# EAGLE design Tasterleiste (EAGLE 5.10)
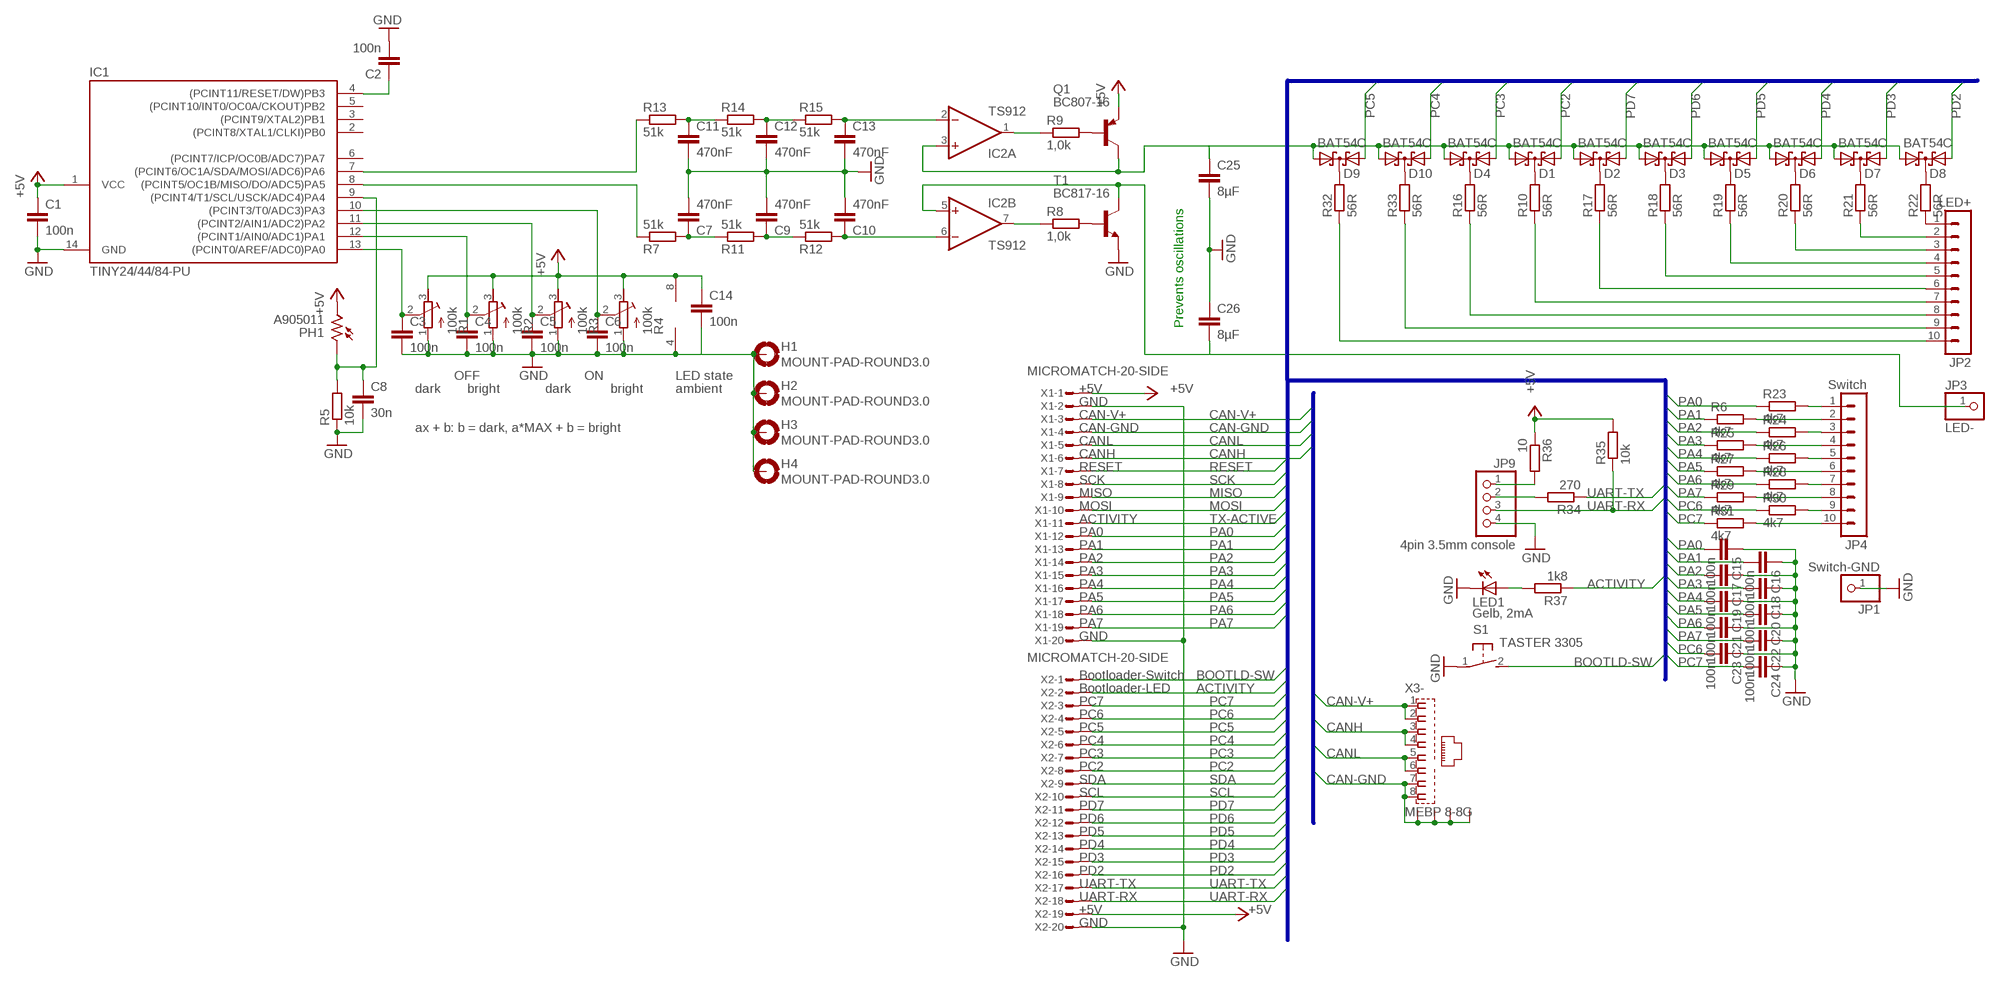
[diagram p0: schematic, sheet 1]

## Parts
C1  100n  C-EUC0805  [C0805]
C2  100n  C-EUC0805  [C0805]
C3  100n  C-EUC0805  [C0805]
C4  100n  C-EUC0805  [C0805]
C5  100n  C-EUC0805  [C0805]
C6  100n  C-EUC0805  [C0805]
C7  470nF  C-EUC0805  [C0805]
C8  30n  C-EUC0805  [C0805]
C9  470nF  C-EUC0805  [C0805]
C10  470nF  C-EUC0805  [C0805]
C11  470nF  C-EUC0805  [C0805]
C12  470nF  C-EUC0805  [C0805]
C13  470nF  C-EUC0805  [C0805]
C14  100n  C-EUC0805  [C0805]
C15  100n  C-EUC0805  [C0805]
C16  100n  C-EUC0805  [C0805]
C17  100n  C-EUC0805  [C0805]
C18  100n  C-EUC0805  [C0805]
C19  100n  C-EUC0805  [C0805]
C20  100n  C-EUC0805  [C0805]
C21  100n  C-EUC0805  [C0805]
C22  100n  C-EUC0805  [C0805]
C23  100n  C-EUC0805  [C0805]
C24  100n  C-EUC0805  [C0805]
C25  8µF  C-EUC0805  [C0805]
C26  8µF  C-EUC0805  [C0805]
D1  BAT54C  [SOT23]
D2  BAT54C  [SOT23]
D3  BAT54C  [SOT23]
D4  BAT54C  [SOT23]
D5  BAT54C  [SOT23]
D6  BAT54C  [SOT23]
D7  BAT54C  [SOT23]
D8  BAT54C  [SOT23]
D9  BAT54C  [SOT23]
D10  BAT54C  [SOT23]
H1  MOUNT-PAD-ROUND3.0  [3,0-PAD]
H2  MOUNT-PAD-ROUND3.0  [3,0-PAD]
H3  MOUNT-PAD-ROUND3.0  [3,0-PAD]
H4  MOUNT-PAD-ROUND3.0  [3,0-PAD]
IC1  TINY24/44/84-PU  [DIL14]
IC2  TS912  LM358N  [DIL08]
JP1  Switch-GND  PINHD-1X1  [1X01]
JP2  LED+  MA10-1  [MA10-1]
JP3  LED-  PINHD-1X1  [1X01]
JP4  Switch  MA10-1  [MA10-1]
JP9  4pin 3.5mm console  PINHD-1X4  [1X04]
LED1  Gelb, 2mA  LED3MM  [LED3MM]
PH1  A905011  A1050_12  [T0-46-A10XX]
Q1  BC807-16  BC807-16-PNP-SOT23-BEC  [SOT23-BEC]
R1  100k  R-TRIMM64W  [RTRIM64W]
R2  100k  R-TRIMM64W  [RTRIM64W]
R3  100k  R-TRIMM64W  [RTRIM64W]
R4  100k  R-TRIMM64W  [RTRIM64W]
R5  10k  R-EU_R0805  [R0805]
R6  4k7  R-EU_0207/10  [0207/10]
R7  51k  R-EU_R0805  [R0805]
R8  1,0k  R-EU_R0805  [R0805]
R9  1,0k  R-EU_R0805  [R0805]
R10  56R  R-EU_0207/10  [0207/10]
R11  51k  R-EU_R0805  [R0805]
R12  51k  R-EU_R0805  [R0805]
R13  51k  R-EU_R0805  [R0805]
R14  51k  R-EU_R0805  [R0805]
R15  51k  R-EU_R0805  [R0805]
R16  56R  R-EU_0207/10  [0207/10]
R17  56R  R-EU_0207/10  [0207/10]
R18  56R  R-EU_0207/10  [0207/10]
R19  56R  R-EU_0207/10  [0207/10]
R20  56R  R-EU_0207/10  [0207/10]
R21  56R  R-EU_0207/10  [0207/10]
R22  56R  R-EU_0207/10  [0207/10]
R23  4k7  R-EU_0207/10  [0207/10]
R24  4k7  R-EU_0207/10  [0207/10]
R25  4k7  R-EU_0207/10  [0207/10]
R26  4k7  R-EU_0207/10  [0207/10]
R27  4k7  R-EU_0207/10  [0207/10]
R28  4k7  R-EU_0207/10  [0207/10]
R29  4k7  R-EU_0207/10  [0207/10]
R30  4k7  R-EU_0207/10  [0207/10]
R31  4k7  R-EU_0207/10  [0207/10]
R32  56R  R-EU_0207/10  [0207/10]
R33  56R  R-EU_0207/10  [0207/10]
R34  270  R-EU_R0805  [R0805]
R35  10k  R-EU_R0805  [R0805]
R36  10  R-EU_R0805  [R0805]
R37  1k8  R-EU_R0805  [R0805]
S1  TASTER 3305  31-XX  [B3F-31XX]
T1  BC817-16  BC817-16-NPN-SOT23-BEC  [SOT23-BEC]
X1  MICROMATCH-20-SIDE  [MICROMATCH-20-SIDE]
X2  MICROMATCH-20-SIDE  [MICROMATCH-20-SIDE]
X3  MEBP 8-8G  RJ45  [RJ45]

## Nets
+5V: C1.1 C14.1 IC1.1(VCC) IC2.8(P:V+) PH1.2 Q1.E R1.3(A) R2.3(A) R3.3(A) R4.3(A) R35.2 R36.1 X1.1 X2.19
ACTIVITY: R37.1 X2.2
ACTIVITY_LED: LED1.A R37.2
BOOTLD-SW: S1.2(S) X2.1
CAN-GND [Power]: X1.4 X3.7 X3.8 X3.G1 X3.G2 X3.G3 X3.G4
CAN-V+ [Power]: X1.3 X3.1 X3.2
CANH: X1.6 X3.3 X3.4
CANL: X1.5 X3.5 X3.6
GND: C1.2 C2.2 C3.2 C4.2 C5.2 C6.2 C7.2 C8.2 C9.2 C10.2 C11.2 C12.2 C13.2 C14.2 C15.1 C16.1 C17.1 C18.1 C19.1 C20.1 C21.1 C22.1 C23.1 C24.1 C25.2 C26.1 H1.B3,0(MOUNT) H2.B3,0(MOUNT) H3.B3,0(MOUNT) H4.B3,0(MOUNT) IC1.14(GND) IC2.4(P:V-) JP1.1 JP9.4 LED1.K(C) R1.1(E) R2.1(E) R3.1(E) R4.1(E) R5.1 S1.1(P) T1.E X1.2 X1.20 X2.20
MISO: X1.9
MOSI: X1.10
N$1: C2.1 IC1.4((PCINT11/RESET/DW)PB3)
N$2: D4.3(CC) R16.2
N$3: IC2.7(B:OUT) R8.1
N$4: IC2.1(A:OUT) R9.1
N$5: IC1.8((PCINT5/OC1B/MISO/DO/ADC5)PA5) R7.1
N$6: IC1.7((PCINT6/OC1A/SDA/MOSI/ADC6)PA6) R13.1
N$7: C3.1 IC1.13((PCINT0/AREF/ADC0)PA0) R1.2(S)
N$8: C4.1 IC1.12((PCINT1/AIN0/ADC1)PA1) R2.2(S)
N$9: C5.1 IC1.11((PCINT2/AIN1/ADC2)PA2) R3.2(S)
N$10: C6.1 IC1.10((PCINT3/T0/ADC3)PA3) R4.2(S)
N$11: C8.1 IC1.9((PCINT4/T1/SCL/USCK/ADC4)PA4) PH1.1 R5.2
N$12: Q1.B R9.2
N$13: R8.2 T1.B
N$14: JP4.1 R23.2
N$16: C7.1 R7.2 R11.1
N$17: C9.1 R11.2 R12.1
N$18: C10.1 IC2.6(B:-IN) R12.2
N$19: C11.1 R13.2 R14.1
N$20: C12.1 R14.2 R15.1
N$21: C13.1 IC2.2(A:-IN) R15.2
N$22: JP2.8 R16.1
N$23: D1.3(CC) R10.2
N$24: JP2.7 R10.1
N$25: JP4.3 R24.2
N$26: D2.3(CC) R17.2
N$27: JP2.6 R17.1
N$28: D3.3(CC) R18.2
N$29: JP2.5 R18.1
N$30: JP4.10 R31.2
N$31: D5.3(CC) R19.2
N$32: JP2.4 R19.1
N$33: D6.3(CC) R20.2
N$34: JP2.3 R20.1
N$35: JP4.2 R6.2
N$36: D7.3(CC) R21.2
N$37: JP2.2 R21.1
N$38: D8.3(CC) R22.2
N$39: JP2.1 R22.1
N$40: JP4.4 R25.2
N$41: JP4.5 R26.2
N$42: JP4.6 R27.2
N$43: JP4.7 R28.2
N$44: JP4.8 R29.2
N$45: JP4.9 R30.2
N$46: JP9.2 R34.2
N$47: JP9.1 R36.2
N$49: D9.3(CC) R32.2
N$50: JP2.10 R32.1
N$51: D10.3(CC) R33.2
N$52: JP2.9 R33.1
N$54: C26.2 IC2.5(B:+IN) JP3.1 T1.C
N$55: C25.1 D1.1(A1) D2.1(A1) D3.1(A1) D4.1(A1) D5.1(A1) D6.1(A1) D7.1(A1) D8.1(A1) D9.1(A1) D10.1(A1) IC2.3(A:+IN) Q1.C
PA0: C15.2 R23.1 X1.12
PA1: C16.2 R6.1 X1.13
PA2: C17.2 R24.1 X1.14
PA3: C18.2 R25.1 X1.15
PA4: C19.2 R26.1 X1.16
PA5: C20.2 R27.1 X1.17
PA6: C21.2 R28.1 X1.18
PA7: C22.2 R29.1 X1.19
PC2: D1.2(A2) X2.8
PC3: D4.2(A2) X2.7
PC4: D10.2(A2) X2.6
PC5: D9.2(A2) X2.5
PC6: C23.2 R30.1 X2.4
PC7: C24.2 R31.1 X2.3
PD2: D8.2(A2) X2.16
PD3: D7.2(A2) X2.15
PD4: D6.2(A2) X2.14
PD5: D5.2(A2) X2.13
PD6: D3.2(A2) X2.12
PD7: D2.2(A2) X2.11
RESET: X1.7
SCK: X1.8
SCL: X2.10
SDA: X2.9
TX-ACTIVE: X1.11
UART-RX: JP9.3 R35.1 X2.18
UART-TX: R34.1 X2.17
Unconnected: IC1.2((PCINT8/XTAL1/CLKI)PB0) IC1.3((PCINT9/XTAL2)PB1) IC1.5((PCINT10/INT0/OC0A/CKOUT)PB2) IC1.6((PCINT7/ICP/OC0B/ADC7)PA7)

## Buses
PA[0..7],PC[2..7],PD[2..7],SCK,MISO,MOSI,CAN-CS,BOOTLD-SW,CAN-INT,TX-ACTIVE,ACTIVITY,SDA,SCL,UART-RX,UART-TX,CLK,RESET
CANL,CANH,CAN-V+,CAN-GND

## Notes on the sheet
- Prevents oscillations
- OFF | ON | LED state
- dark | bright | dark | bright | ambient | +5V
- GND
- CAN-V+
- ax + b: b = dark, a*MAX + b = bright | CAN-GND
- CANL
- CANH
- RESET
- SCK
- MISO
- MOSI
- ACTIVITY
- PA0
- PA1
- PA2
- PA3
- PA4
- PA5
- PA6
- PA7
- GND
- Bootloader-Switch
- Bootloader-LED
- PC7
- PC6
- PC5
- PC4
- PC3
- PC2
- SDA
- SCL
- PD7
- PD6
- PD5
- PD4
- PD3
- PD2
- UART-TX
- UART-RX
- +5V
- GND

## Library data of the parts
C1-C26 = rcl:C-EU: CAPACITOR, European symbol
D1-D10 = diode:BAT54C: Schottky Diodes Source: Fairchild .. BAT54.pdf
H1-H4 = holes:MOUNT-PAD-ROUND: MOUNTING PAD, round
IC1 = avr-6:TINY24/44/84
IC2 = linear:LM358: OP AMP also LM158; LM258; LM2904 Source: http://cache.national.com/ds/LM/LM158.pdf
JP1 JP3 = pinhead:PINHD-1X1: PIN HEADER
JP2 JP4 = con-lstb:MA10-1: PIN HEADER
JP9 = pinhead:PINHD-1X4: PIN HEADER
LED1 = led:LED: LED
PH1 = photo-elements:A10: Sensor Robust Light Sensing Applications
Q1 = transistor:*-PNP-: PNP Transistror
R1-R4 = rcl:R-TRIMM: Trimm resistor
R5-R37 = rcl:R-EU_: RESISTOR, European symbol
S1 = switch-omron:31-XX: OMRON SWITCH
T1 = transistor:*-NPN-: NPN Transistror BF959 corrected 2008.03.06
X1 X2 = apbteam_con-amp-micromatch:MICROMATCH-20: Micro-MaTch 20 Straight connector: Suited for both, female and male.
X3 = con-appsys:RJ45: AMP connector

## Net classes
1 Power: width 0.5 mm

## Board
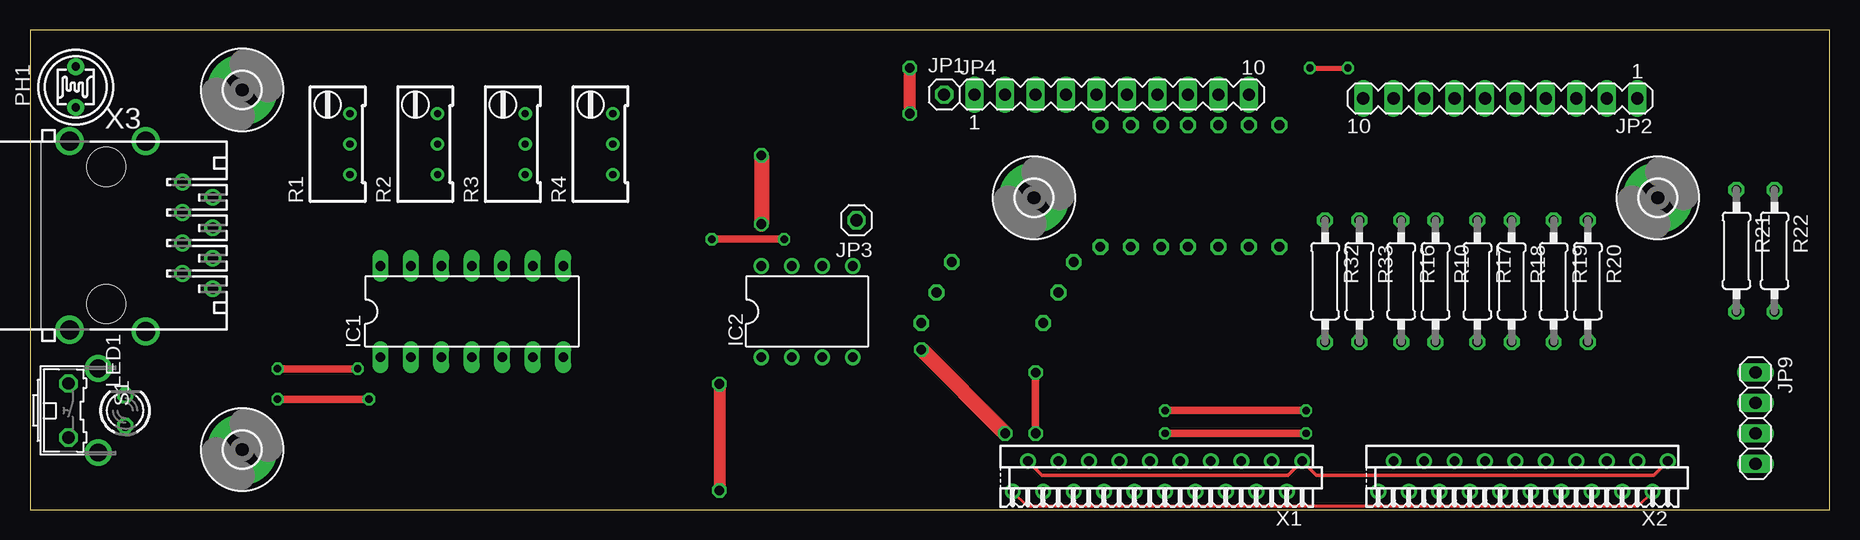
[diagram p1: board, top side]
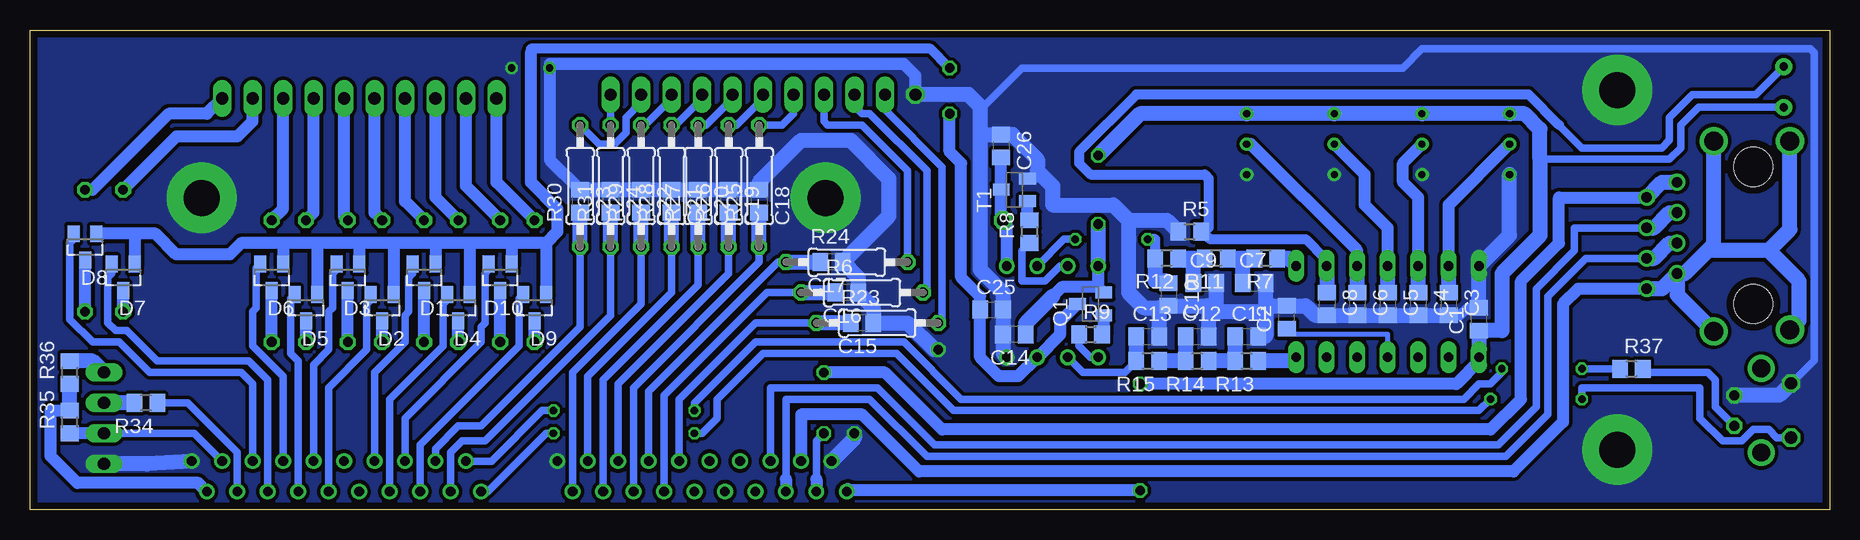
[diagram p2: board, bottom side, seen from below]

Size 150 x 40 mm. Coordinates in mm from the lower left corner, seen from the top.
Outline: 0,0 150,0 150,40 0,40 0,0
Copper layers (1*16): Top 0.035mm / dielectric 1.5mm / Bottom 0.035mm
Design rules "default *": minimum track width 10mil, minimum drill 24mil, track to track 0.3mm, track to pad 0.3mm, pad to pad 0.3mm, via to via 0.3mm, smd to smd 0.2mm, copper to edge 0.6mm, drill to drill 8mil, minimum pad ring 10mil, minimum via ring 8mil, stop-mask expansion 4mil, vias tented up to drill 0mil, thermal gap 10mil

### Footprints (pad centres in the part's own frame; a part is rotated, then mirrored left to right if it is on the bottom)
C0805 = smd 1.3 x 1.5: 1 -0.95,0; 2 0.95,0
SOT23 = smd 1 x 1.4: 1 -0.95,-1.1; 2 0.95,-1.1; 3 0,1.1
3,0-PAD = drill 3 pad 5.842 round: B3,0 0,0
DIL14 = drill 0.813 long: 1 -7.62,-3.81; 2 -5.08,-3.81; 3 -2.54,-3.81; 4 0,-3.81; 5 2.54,-3.81; 6 5.08,-3.81; 7 7.62,-3.81; 8 7.62,3.81; 9 5.08,3.81; 10 2.54,3.81; 11 0,3.81; 12 -2.54,3.81; 13 -5.08,3.81; 14 -7.62,3.81
DIL08 = drill 0.813 pad 1.27 round: 1 -3.81,-3.81; 2 -1.27,-3.81; 3 1.27,-3.81; 4 3.81,-3.81; 5 3.81,3.81; 6 1.27,3.81; 7 -1.27,3.81; 8 -3.81,3.81
1X01 = drill 1.016 octagon: 1 0,0
MA10-1 = drill 1.016 long: 1 -11.43,0; 2 -8.89,0; 3 -6.35,0; 4 -3.81,0; 5 -1.27,0; 6 1.27,0; 7 3.81,0; 8 6.35,0; 9 8.89,0; 10 11.43,0
1X04 = drill 1.016 long: 1 -3.81,0; 2 -1.27,0; 3 1.27,0; 4 3.81,0
LED3MM = drill 0.813 octagon: A -1.27,0; K 1.27,0
T0-46-A10XX = drill 0.7 pad 1.4 round: 1 -1.7,0; 2 1.7,0
SOT23-BEC = smd 1 x 1.4: B -0.95,-1.1; C 0,1.1; E 0.95,-1.1
RTRIM64W = drill 0.61 round: 1 1.27,-2.54; 2 1.27,0; 3 1.27,2.54
R0805 = smd 1.3 x 1.5: 1 -0.95,0; 2 0.95,0
0207/10 = drill 0.813 octagon: 1 -5.08,0; 2 5.08,0
B3F-31XX = drill 1.016 octagon: 1 -2.261,-1.245; 2 2.261,-1.245 | drill 1.499 pad 2.159 round: 3 -3.505,1.245; 4 3.505,1.245
MICROMATCH-20-SIDE = drill 0.813 round: 1 12.065,1.27; 2 10.795,-1.27; 3 9.525,1.27; 4 8.255,-1.27; 5 6.985,1.27; 6 5.715,-1.27; 7 4.445,1.27; 8 3.175,-1.27; 9 1.905,1.27; 10 0.635,-1.27; 11 -0.635,1.27; 12 -1.905,-1.27; 13 -3.175,1.27; 14 -4.445,-1.27; 15 -5.715,1.27; 16 -6.985,-1.27; 17 -8.255,1.27; 18 -9.525,-1.27; 19 -10.795,1.27; 20 -12.065,-1.27
RJ45 = drill 0.889 round: 1 -4.445,6.35; 2 -3.175,8.89; 3 -1.905,6.35; 4 -0.635,8.89; 5 0.635,6.35; 6 1.905,8.89; 7 3.175,6.35; 8 4.445,8.89 | drill 1.575 pad 2.184 round: G1 -7.874,-3.048; G2 7.874,-3.048; G3 -7.874,3.302; G4 8.001,3.302 | hole 3.251: -5.715,0; 5.715,0

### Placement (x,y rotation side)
C1  29.21,15.88 90 bottom
C2  45.24,16.03 90 bottom
C3  31.75,17.14 270 bottom
C4  34.29,17.14 270 bottom
C5  36.83,17.14 270 bottom
C6  39.37,17.14 270 bottom
C7  47.94,18.89 0 bottom
C8  41.91,17.14 270 bottom
C9  52.07,18.89 0 bottom
C10  55.09,17.94 270 bottom
C11  48.58,14.45 0 bottom
C12  52.7,14.45 0 bottom
C13  56.83,14.45 0 bottom
C14  67.94,14.61 180 bottom
C15  80.64,15.56 180 bottom
C16  81.92,18.1 180 bottom
C17  83.19,20.64 180 bottom
C18  89.22,25.72 270 bottom
C19  91.76,25.72 270 bottom
C20  94.3,25.72 270 bottom
C21  96.52,25.72 270 bottom
C22  99.06,25.72 270 bottom
C23  104.14,25.72 270 bottom
C24  101.6,25.72 270 bottom
C25  69.85,16.67 0 bottom
C26  69.06,30.32 270 bottom
D1  117.16,19.37 180 bottom
D2  120.65,16.83 180 bottom
D3  123.51,19.37 180 bottom
D4  114.3,16.83 180 bottom
D5  127,16.83 180 bottom
D6  129.86,19.37 180 bottom
D7  142.24,19.37 180 bottom
D8  145.41,21.91 180 bottom
D9  107.95,16.83 180 bottom
D10  110.81,19.37 180 bottom
H1  135.69,26 0 top
H2  83.69,26 0 top
H3  17.69,5 0 top
H4  17.69,35 0 top
IC1  36.83,16.51 0 top
IC2  64.77,16.51 0 top
JP1  76.2,34.61 0 top
JP2  122.56,34.29 180 top
JP3  68.9,24.13 180 top
JP4  90.17,34.61 0 top
JP9  143.83,7.62 270 top
LED1  7.94,8.26 90 top
PH1  3.81,35.24 270 top
Q1  61.59,17.14 90 bottom
R1  25.4,30.48 0 top
R2  32.7,30.48 0 top
R3  40.01,30.48 0 top
R4  47.31,30.48 0 top
R5  53.34,23.18 0 bottom
R6  80.64,18.1 0 bottom
R7  46.99,20.95 180 bottom
R8  66.67,23.18 90 bottom
R9  61.59,14.61 0 bottom
R10  117.16,19.05 270 top
R11  51.12,20.95 180 bottom
R12  55.24,20.95 180 bottom
R13  48.58,12.38 180 bottom
R14  52.7,12.38 180 bottom
R15  56.83,12.38 180 bottom
R16  114.3,19.05 270 top
R17  120.65,19.05 270 top
R18  123.51,19.05 270 top
R19  127,19.05 270 top
R20  129.86,19.05 270 top
R21  142.24,21.59 270 top
R22  145.41,21.59 270 top
R23  79.38,15.56 0 bottom
R24  81.92,20.64 0 bottom
R25  89.22,26.99 90 bottom
R26  91.76,26.99 90 bottom
R27  94.3,26.99 90 bottom
R28  96.52,26.99 90 bottom
R29  99.06,26.99 90 bottom
R30  104.14,26.99 90 bottom
R31  101.6,26.99 90 bottom
R32  107.95,19.05 270 top
R33  110.81,19.05 270 top
R34  140.34,8.89 180 bottom
R35  146.69,7.3 90 bottom
R36  146.69,11.43 90 bottom
R37  16.51,11.75 0 bottom
S1  4.45,8.26 270 top
T1  67.94,26.67 90 bottom
X1  93.98,2.77 180 top
X2  124.46,2.77 180 top
X3  6.35,22.86 270 top

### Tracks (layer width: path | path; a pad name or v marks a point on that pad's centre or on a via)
+5V  (via drill 0.8)
  Top 0.254: X1.1 83.1,0.32 134.07,0.32 X2.19
  Top 1.016: v57.47,10.48 v57.47,1.59
  Top 1.27: v60.96,29.53 v60.96,23.81
  Bottom 0.61: PH1.2 10.91,33.54 12.38,32.07 12.38,30.16 13.34,29.21 24.13,29.21
  Bottom 1.016: IC2.8 60.96,18.56 | 64.77,17.78 63.99,18.56 60.96,18.56 | R35.2 148.27,8.25 148.27,8.26 148.27,4.45 146.05,2.22 135.98,2.22 X2.19 | 29.21,12.38 31.11,10.48 v57.47,10.48 | v57.47,1.59 81.83,1.59 | 60.96,18.56 Q1.E
  Bottom 1.27: 64.77,17.78 67,15.55 C14.1 | v60.96,23.81 IC2.8 | R35.2 R36.1 | 29.21,12.38 IC1.1 C1.1 27.3,14.93 27.3,19.68 24.13,22.86 24.13,29.21 24.13,31.75 25.4,33.02 R1.3 R2.3 R3.3 R4.3 57.47,33.02 v60.96,29.53 | 81.83,1.59 X1.1
ACTIVITY  (via drill 0.61)
  Top 0.61: v20.64,11.75 v27.3,11.75 | v94.61,8.26 v106.36,8.26
  Bottom 0.61: R37.1 v20.64,11.75 | v27.3,11.75 27.3,11.43 28.26,10.48 29.21,10.48 30.48,9.21 72.39,9.21 77.15,13.97 89.53,13.97 94.61,8.89 v94.61,8.26 | v106.36,8.26 107.31,8.26 111.53,4.04 X2.2
ACTIVITY_LED
  Bottom 0.61: LED1.A 9.53,8.57 9.53,10.79 10.16,11.43 15.56,11.43 R37.2
BOOTLD-SW  (via drill 0.61)
  Top 0.61: v94.61,6.35 v106.36,6.35 | v20.64,9.21 v28.26,9.21
  Bottom 0.61: v106.36,6.35 107,6.35 111.85,1.5 X2.1 | S1.2 4.41,5.99 5.08,6.67 6.35,6.67 7.3,5.71 8.89,5.71 10.79,7.62 10.79,10.16 20.64,10.16 v20.64,9.21 | v28.26,9.21 29.21,8.26 73.03,8.26 77.79,13.02 88.9,13.02 92.71,9.21 92.71,7.62 93.98,6.35 v94.61,6.35
CAN-GND
  Bottom 1.016: X3.8 20.95,18.41 22.23,17.14 22.23,7.3 26.35,3.17 75.88,3.17 80.64,7.94 85.72,7.94 X1.4
  Bottom 1.27: X3.7 12.7,17.91 X3.G4 | X3.7 12.06,19.68 10.16,21.59 | 10.16,21.59 9.65,22.1 X3.G3 | X3.G2 2.54,15.75 2.54,19.05 5.08,21.59 | 5.08,21.59 10.16,21.59 | X3.G1 3.3,23.37 5.08,21.59 | X3.7 13.97,18.41 X3.8
CAN-V+  (via drill 0.8)
  Top 0.61: v83.82,11.43 v83.82,6.35
  Bottom 0.61: v83.82,6.35 84.45,5.71 84.45,2.54
  Bottom 1.016: X3.2 22.54,26.04 22.54,22.23 25.72,19.05 25.72,9.21 28.26,6.67 73.98,6.67 78.74,11.43 v83.82,11.43 | 84.45,2.54 X1.3
  Bottom 1.27: X3.1 13.97,27.3 X3.2
CANH
  Bottom 0.61: X3.4 21.27,23.5 21.27,21.59 24.45,18.41 24.45,8.57 27.62,5.4 74.61,5.4 79.38,10.16 88.27,10.16 X1.6
  Bottom 1.27: X3.3 13.34,24.77 14.61,23.5 X3.4
CANL
  Bottom 0.61: X3.6 20.32,20.95 23.5,17.78 23.5,7.94 26.99,4.45 75.25,4.45 80.01,9.21 87,9.21 87,2.54
  Bottom 1.016: 87,2.54 X1.5
  Bottom 1.27: X3.5 13.34,22.23 14.61,20.95 X3.6
GND  (via drill 0.61, 0.8)
  Top 0.305: X2.20 135.34,2.86 107.23,2.86 X1.20 104.86,2.86 84.37,2.86 X1.2
  Top 0.406: v106.68,36.83 v109.86,36.83
  Top 1.27: v74.3,13.34 v81.28,6.35
  Bottom 0.61: S1.1 1.27,12.45 1.27,38.1 1.59,38.42 33.97,38.42 35.56,36.83 67.31,36.83 70.48,33.66 70.8,33.66
  Bottom 0.813: C3.2 30.8,16.2 30.16,16.82 C1.2
  Bottom 1.016: C23.1 106.68,29.21 v106.68,36.83 106.68,37.15 77.15,37.15 76.2,36.2 JP1.1 | T1.E 66.36,27.62 65.88,28.1 | C25.2 68.9,17.77 68.89,17.78
  Bottom 1.27: C3.2 C4.2 C5.2 C6.2 C8.2 42.87,16.2 43.65,16.98 C2.2 46.52,16.98 46.99,16.51 | C1.2 IC1.14 26.67,22.86 R1.1 | IC2.4 68.89,13.02 C14.2 68.89,17.78 68.89,18.09 70.8,20 70.8,31.27 | LED1.K 4.19,9.53 S1.1 | X1.2 81.28,5.95 v81.28,6.35 | C23.1 C24.1 C22.1 C21.1 C20.1 C19.1 C18.1 89.22,27.3 85.72,30.8 81.6,30.8 78.42,27.62 78.42,24.45 C17.1 80.97,19.37 C16.1 79.69,16.83 C15.1 76.83,15.56 74.61,13.34 v74.3,13.34 | JP1.1 71.75,34.61 70.8,33.66 70.8,31.27 | JP9.4 140.25,3.81 X2.20 | 58.42,24.13 59.69,25.4 64.77,25.4 64.77,26.99 65.88,28.1 66.04,28.26 66.04,29.21 68.1,31.27 C26.1 70.8,31.27 | R5.1 55.24,24.13 58.42,24.13 | C11.2 46.99,14.45 46.99,16.51 | 46.99,16.51 C7.2 | 55.88,16.51 55.88,16.83 57.15,16.83 58.42,18.1 58.42,24.13 | 55.88,16.51 C13.2 | 51.76,16.51 C12.2 | 51.76,16.51 51.76,16.83 51.91,16.99 C10.2 55.4,16.99 55.88,16.51 | 51.12,16.51 46.99,16.51 | 51.12,16.51 C9.2 | 51.76,16.51 51.12,16.51
  pour Bottom (isolate 0.3, rank 5, no thermals): 0,40 0,0 150,0 150,40
N$1
  Bottom 0.406: IC1.4 36.83,14.61 44.77,14.61 C2.1
N$2
  Bottom 1.016: R16.2 D4.3
N$3
  Bottom 0.61: IC2.7 64.14,20.32 65.41,19.05 67.31,19.05 67.31,21.59 R8.1
N$4
  Bottom 0.61: R9.1 62.55,13.65 61.59,12.7 IC2.1
N$5
  Bottom 1.27: IC1.8 45.09,20.95 R7.1
N$6
  Bottom 1.27: R13.1 44.77,12.38 IC1.7
N$7
  Bottom 1.016: R1.2 31.75,25.4 IC1.13
  Bottom 1.27: C3.1 IC1.13
N$8
  Bottom 1.016: R2.2 35.56,28.89 35.56,27.3 34.29,26.04 IC1.12
  Bottom 1.27: C4.1 IC1.12
N$9
  Bottom 1.016: IC1.11 36.83,23.5 38.73,25.4 38.73,27.94 R3.2
  Bottom 1.27: C5.1 IC1.11
N$10
  Bottom 1.016: IC1.10 39.37,21.59 48.26,30.48 R4.2
  Bottom 1.27: C6.1 IC1.10
N$11
  Bottom 0.61: 22.54,32.07 20.64,30.16 13.97,30.16 13.34,30.8 13.34,32.7 11.43,34.61 6.14,34.61 PH1.1
  Bottom 0.813: 22.54,32.07 25.08,34.61 57.78,34.61 62.55,29.84 62.55,28.89 61.59,27.94 52.07,27.94 51.75,27.62 51.75,23.5 R5.2 51.6,22.54 43.66,22.54 42.07,20.95 IC1.9
  Bottom 1.27: IC1.9 C8.1
N$12
  Bottom 1.016: Q1.B 60.49,14.76 R9.2
N$13
  Bottom 1.016: T1.B 66.84,24.3 R8.2
N$14
  Bottom 0.61: JP4.1 78.74,33.34 73.98,28.57 73.98,15.88 R23.2
N$16
  Bottom 1.27: R11.1 R7.2 48.89,20.95 C7.1
N$17
  Bottom 1.27: 53.02,20.95 R11.2 | C9.1 53.02,20.95 | 53.02,20.95 R12.1
N$18  (via drill 0.61)
  Top 0.61: v56.83,22.54 v62.87,22.54
  Bottom 0.61: v62.87,22.54 63.82,22.54 IC2.6
  Bottom 0.813: v56.83,22.54 56.2,22.54 R12.2
  Bottom 1.27: C10.1 55.24,19.05 56.2,19.05 R12.2
N$19
  Bottom 1.27: R13.2 R14.1 | R13.2 C11.1 | R13.2
N$20
  Bottom 1.27: R15.1 R14.2 C12.1
N$21
  Bottom 0.61: IC2.2 62.23,11.43 58.73,11.43 R15.2
  Bottom 1.27: R15.2 C13.1
N$22
  Bottom 1.016: R16.1 116.2,26.04 JP2.8
N$23
  Bottom 1.016: R10.2 D1.3
N$24
  Bottom 1.016: R10.1 118.75,25.72 JP2.7
N$25
  Bottom 0.61: R24.2 76.83,28.26 80.64,32.07 83.5,32.07 83.82,32.38 JP4.3
N$26
  Bottom 1.016: R17.2 D2.3
N$27
  Bottom 1.016: R17.1 121.28,24.77 JP2.6
N$28
  Bottom 1.016: R18.2 D3.3
N$29
  Bottom 1.016: R18.1 123.83,24.45 JP2.5
N$30
  Bottom 0.61: R31.2 JP4.10
N$31
  Bottom 1.016: R19.2 D5.3
N$32
  Bottom 1.016: R19.1 126.36,24.77 JP2.4
N$33
  Bottom 1.016: R20.2 D6.3
N$34
  Bottom 1.016: R20.1 128.91,25.08 JP2.3
N$35
  Bottom 0.61: 81.28,34.29 JP4.2 81.28,33.66 80.64,33.02 80.01,33.02 75.25,28.26 75.25,18.41 R6.2
N$36
  Bottom 1.016: R21.2 D7.3
N$37
  Bottom 1.016: JP2.2 131.44,32.38 132.72,31.11 137.79,31.11 R21.1
N$38
  Bottom 1.016: D8.3 R22.2 145.41,18.76
N$39
  Bottom 1.016: JP2.1 135.25,33.02 138.43,33.02 144.78,26.67 R22.1
N$40
  Bottom 0.61: R25.2 87.31,32.07 86.36,33.02 JP4.4
N$41
  Bottom 0.61: R26.2 91.12,32.07 88.9,34.29 JP4.5
N$42
  Bottom 0.61: R27.2 93.66,32.07 91.44,34.29 JP4.6
N$43
  Bottom 0.61: R28.2 96.2,32.07 93.98,34.29 JP4.7
N$44
  Bottom 0.61: R29.2 98.74,32.07 96.52,34.29 JP4.8
N$45
  Bottom 0.61: R30.2 102.55,30.48 101.28,30.48 100.33,31.43 100.33,32.7 99.06,33.97 JP4.9
N$46
  Bottom 1.27: R34.2 JP9.2
N$47
  Bottom 1.27: JP9.1 144.78,12.38 R36.2
N$49
  Bottom 1.016: R32.2 D9.3
N$50
  Bottom 1.016: R32.1 111.12,27.3 JP2.10
N$51
  Bottom 1.016: R33.2 D10.3
N$52
  Bottom 1.016: R33.1 113.67,26.99 JP2.9
N$54
  Bottom 1.016: IC2.5 68.58,23.81 JP3.1 69.05,24.28 T1.C 69.05,29.36 C26.2
N$55  (via drill 0.8)
  Top 1.016: v73.34,33.02 v73.34,36.83
  Bottom 0.813: 108.27,38.1 108.27,38.42 74.93,38.42 v73.34,36.83
  Bottom 1.016: Q1.C 63.97,15.88 64.14,15.88 64.14,14.61 IC2.3 67.63,11.11 69.22,11.11 70.8,12.7 C25.1 70.8,17.78 72.39,19.37 72.39,28.89 73.34,29.84 v73.34,33.02 | 116.21,22.23 D1.1 | 128.91,22.23 D6.1 | D4.1 113.35,21.91 113.03,22.23 | 109.86,22.23 D10.1 | 109.86,22.23 113.03,22.23 | 107,22.23 D9.1 | 107,22.23 109.86,22.23 | 108.27,38.1 108.27,27.3 106.05,25.08 106.05,23.18 107,22.23 | 113.03,22.23 116.2,22.23 116.21,22.23 | 116.21,22.23 119.7,22.23 | 119.7,22.23 D2.1 | 119.7,22.23 122.56,22.23 | 122.56,22.23 D3.1 | 126.05,22.23 128.91,22.23 | 126.05,22.23 D5.1 | 122.56,22.23 126.05,22.23 | 128.91,22.23 132.4,22.23 133.35,21.27 137.79,21.27 139.53,23.01 140.97,23.01 | 140.97,23.01 D8.1 | D7.1 141.29,22.69 140.97,23.01
PA0
  Bottom 0.61: X1.12 95.89,9.21 89.53,15.56 R23.1
  Bottom 1.27: C15.2 R23.1
PA1
  Bottom 0.61: X1.13 97.16,9.53 88.58,18.1 R6.1
  Bottom 1.27: R6.1 C16.2
PA2
  Bottom 0.61: X1.14 98.42,9.84 87.63,20.64 R24.1
  Bottom 1.27: R24.1 C17.2
PA3
  Bottom 0.61: X1.15 99.69,10.16 89.22,20.64 R25.1
  Bottom 1.27: R25.1 C18.2
PA4
  Bottom 0.61: X1.16 100.97,10.48 91.76,19.68 R26.1
  Bottom 1.27: R26.1 C19.2
PA5
  Bottom 0.61: X1.17 102.23,10.79 94.3,18.73 R27.1
  Bottom 1.27: R27.1 C20.2
PA6
  Bottom 0.61: X1.18 103.5,11.11 96.52,18.1 R28.1
  Bottom 1.27: R28.1 C21.2
PA7
  Bottom 0.61: X1.19 104.78,11.43 99.06,17.14 R29.1
  Bottom 1.27: R29.1 C22.2
PC2
  Bottom 0.61: D1.2 118.11,19.69 118.43,19.37 118.43,16.51 118.75,16.19 118.75,13.97 121.28,11.43 X2.8
PC3
  Bottom 0.61: D4.2 115.25,17.46 115.57,17.14 115.57,13.65 120.02,9.21 X2.7
PC4
  Bottom 0.61: D10.2 111.76,20 112.08,19.68 112.08,15.56 112.39,15.24 112.39,13.97 118.75,7.62 X2.6
PC5
  Bottom 0.61: D9.2 109.22,17.61 109.22,13.65 117.47,5.4 X2.5
PC6
  Bottom 0.61: R30.1 104.14,15.24 112.39,6.99 114.3,6.99 116.2,5.08 X2.4
  Bottom 1.27: R30.1 C23.2
PC7
  Bottom 0.61: X2.3 114.94,4.76 113.98,5.71 112.08,5.71 101.6,16.19 R31.1
  Bottom 1.27: R31.1 C24.2
PD2
  Bottom 0.61: D8.2 146.37,22.55 146.69,22.23 146.69,15.88 144.78,13.97 142.56,13.97 140.02,11.43 132.4,11.43 131.44,10.48 X2.16
PD3
  Bottom 0.61: X2.15 130.18,10.79 131.76,12.38 139.38,12.38 141.92,14.92 142.88,14.92 143.51,15.56 143.51,19.37 143.19,19.69 D7.2
PD4
  Bottom 0.61: D6.2 131.13,20.15 131.13,16.83 131.44,16.51 131.44,13.65 128.91,11.11 X2.14
PD5
  Bottom 0.61: X2.13 127.64,12.38 128.27,13.02 128.27,17.61 D5.2
PD6
  Bottom 0.61: D3.2 124.46,20 124.78,19.68 124.78,16.83 125.09,16.51 125.09,13.34 126.36,12.06 X2.12
PD7
  Bottom 0.61: D2.2 121.6,17.46 121.92,17.14 121.92,13.34 125.09,10.16 X2.11
UART-RX
  Bottom 0.61: X2.18 136.29,6.35 JP9.3
  Bottom 1.016: JP9.3 R35.1
  Bottom 1.27: R35.1
UART-TX
  Bottom 0.61: X2.17 132.72,4.76 136.84,8.89 R34.1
